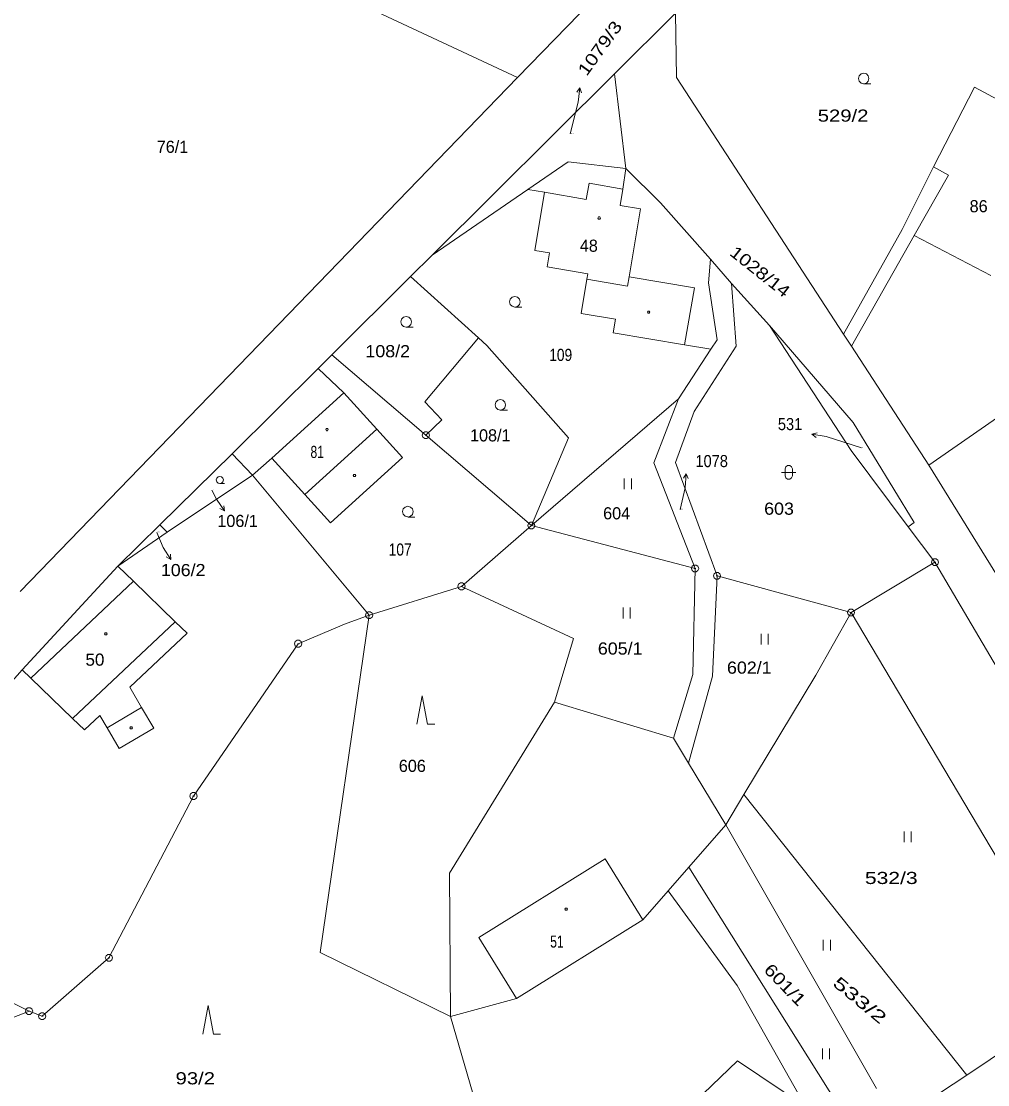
# Model space of a CAD drawing. Extents: x -687390 to -684106, y -954833 to -951648.
# Drawn here: x -687069.7 to -686934.3, y -952895.8 to -952746.6 of the extents above; entities that cross this region are included whole.
import ezdxf
from ezdxf.enums import TextEntityAlignment as Align

# ---------------------------------------------------------------- set-up
doc = ezdxf.new("R2010")
doc.units = 0
doc.header["$LTSCALE"] = 0.68
for name, color, linetype, lineweight in [('1', 7, 'Continuous', 13), ('3', 7, 'Continuous', 13), ('4', 7, 'Continuous', 13), ('5', 7, 'Continuous', 13), ('7', 7, 'Continuous', 13), ('8', 7, 'Continuous', 13)]:
    doc.layers.add(name, color=color, linetype=linetype, lineweight=lineweight)
doc.layers.add('2', color=7, linetype='Continuous')

msp = doc.modelspace()

# ---------------------------------------------------------------- linework, layer by layer
at = {"layer": '1'}
for p, q in [((-687044.3, -952733.87), (-687000.19, -952754.54)), ((-686978.03, -952745.51), (-686986.58, -952754.02)), ((-686984.99, -952767.3), (-686986.58, -952754.02)), ((-686921.94, -952763.55), (-686936.14, -952755.87)), ((-686984.99, -952767.3), (-686993.1, -952766.34)), ((-686984.99, -952767.3), (-686980.16, -952772.08)), ((-686996.42, -952770.6), (-686998.74, -952770.21)), ((-686980.16, -952772.08), (-686973.12, -952780)), ((-686954.5, -952790.5), (-686946.27, -952775.82)), ((-686944.59, -952776.68), (-686953.39, -952792.2)), ((-686933.85, -952782.3), (-686944.59, -952776.68)), ((-687015.17, -952782.45), (-687026.22, -952793.42)), ((-687015.17, -952782.45), (-687005.65, -952791.03)), ((-686964.87, -952789.29), (-686953.14, -952802.92)), ((-687005.65, -952791.03), (-687004.48, -952792.09)), ((-686986.77, -952790.31), (-686976.76, -952792)), ((-686973.08, -952792.63), (-686976.76, -952792)), ((-687026.22, -952793.42), (-687013.03, -952804.69)), ((-687024.54, -952798.73), (-687028.14, -952795.33)), ((-687024.54, -952798.73), (-687019.92, -952803.82)), ((-686998.24, -952817.35), (-686977.64, -952799.56)), ((-686977.64, -952799.56), (-686981.08, -952808.54)), ((-686944.6, -952816.91), (-686953.14, -952802.92)), ((-687019.92, -952803.82), (-687016.32, -952807.8)), ((-687013.03, -952804.69), (-686998.24, -952817.35)), ((-687040.16, -952807.28), (-687037.34, -952810.27)), ((-687037.34, -952810.27), (-687034.64, -952807.89)), ((-687030.01, -952812.99), (-687034.64, -952807.89)), ((-687026.41, -952816.95), (-687016.32, -952807.8)), ((-686975.29, -952823.36), (-686981.08, -952808.54)), ((-687037.34, -952810.27), (-687020.98, -952829.91)), ((-687030.01, -952812.99), (-687026.41, -952816.95)), ((-687050.32, -952817.26), (-687049.31, -952818.29)), ((-686944.6, -952816.91), (-686945.41, -952817.51)), ((-686972.22, -952824.4), (-686972.87, -952838.46)), ((-687020.98, -952829.91), (-687024.42, -952831.17)), ((-686958.39, -952838.32), (-686953.43, -952829.54)), ((-686953.43, -952829.54), (-686920.81, -952884.49)), ((-687048.15, -952830.85), (-687046.5, -952832.45)), ((-687030.92, -952833.92), (-687024.42, -952831.17)), ((-687046.5, -952832.45), (-687054.54, -952840.02)), ((-687068.42, -952838.73), (-687069.6, -952837.58)), ((-686972.87, -952838.46), (-686976.2, -952850.66)), ((-687052.87, -952842.84), (-687054.54, -952840.02)), ((-687051.15, -952845.76), (-687052.87, -952842.84)), ((-687058.74, -952843.97), (-687060.9, -952846.01)), ((-687058.74, -952843.97), (-687057.72, -952845.7)), ((-687057.72, -952845.7), (-687056, -952848.63)), ((-687056, -952848.63), (-687051.15, -952845.76)), ((-686968.45, -952855.08), (-686937.22, -952894.39)), ((-686970.99, -952859.32), (-686949.85, -952896.26)), ((-686955.03, -952899), (-686976.16, -952865.23)), ((-686979.07, -952868.55), (-686969.38, -952881.84)), ((-687068.64, -952885.43), (-687097.68, -952871.23))]:
    msp.add_line(p, q, dxfattribs=at)
for points in [[(-686977.91, -952754.52), (-686978.03, -952745.51), (-686968.52, -952733.75)], [(-686986.33, -952740.23), (-687000.19, -952754.54), (-687069.88, -952826.59)], [(-686986.58, -952754.02), (-687012.16, -952779.46), (-687015.17, -952782.45)], [(-686977.91, -952754.52), (-686954.5, -952790.5), (-686953.39, -952792.2), (-686942.54, -952808.88)], [(-686936.14, -952755.87), (-686941.89, -952767.04), (-686946.27, -952775.82)], [(-686993.1, -952766.34), (-686998.74, -952770.21), (-687012.16, -952779.46)], [(-686996.42, -952770.6), (-686997.76, -952778.78), (-686995.69, -952779.12), (-686996.02, -952781.09), (-686990.33, -952782.04)], [(-686942.54, -952808.88), (-686900.19, -952779.49), (-686902.11, -952775.53)], [(-686973.12, -952780), (-686970.18, -952783.41), (-686969.53, -952792.18), (-686975.41, -952801.38), (-686978.06, -952808.49), (-686972.22, -952824.4)], [(-686972.21, -952791.3), (-686973.43, -952783.33), (-686973.12, -952780)], [(-686990.33, -952782.04), (-686990.46, -952782.82), (-686991.26, -952787.62)], [(-686970.18, -952783.41), (-686964.87, -952789.29), (-686953.42, -952806.81)], [(-686991.26, -952787.62), (-686986.45, -952788.42), (-686986.77, -952790.31)], [(-687013.03, -952804.69), (-687010.77, -952802.53), (-687013.19, -952800.02), (-687005.65, -952791.03)], [(-686998.24, -952817.35), (-686993.04, -952805.03), (-687004.48, -952792.09)], [(-686977.64, -952799.56), (-686973.08, -952792.63), (-686972.21, -952791.3)], [(-687026.22, -952793.42), (-687028.14, -952795.33), (-687040.16, -952807.28)], [(-687056.2, -952823.03), (-687050.32, -952817.26), (-687040.16, -952807.28)], [(-686941.67, -952822.48), (-686945.41, -952817.51), (-686953.42, -952806.81)], [(-686942.54, -952808.88), (-686931.71, -952826.41), (-686920.73, -952825.17)], [(-687056.2, -952823.03), (-687049.31, -952818.29), (-687037.34, -952810.27)], [(-687020.98, -952829.91), (-687008.03, -952825.88), (-686998.24, -952817.35), (-686975.29, -952823.36)], [(-686972.22, -952824.4), (-686953.43, -952829.54), (-686941.67, -952822.48)], [(-686901.42, -952870.78), (-686906.16, -952871.49), (-686915.95, -952866.19), (-686941.67, -952822.48)], [(-687076.25, -952845.06), (-687069.6, -952837.58), (-687056.2, -952823.03)], [(-687056.2, -952823.03), (-687054.02, -952825.15), (-687048.15, -952830.85)], [(-687008.03, -952825.88), (-686992.32, -952833.2), (-686995.02, -952842.1), (-686978.32, -952847.16), (-686975.61, -952838.21), (-686975.29, -952823.36)], [(-687009.56, -952886.19), (-687027.83, -952877.22), (-687020.98, -952829.91)], [(-687069.27, -952916.95), (-687084.32, -952891.61), (-687068.64, -952885.43), (-687066.8, -952886.15), (-687057.45, -952877.97), (-687045.6, -952855.28), (-687030.92, -952833.92)], [(-687060.9, -952846.01), (-687062.55, -952844.41), (-687068.42, -952838.73)], [(-686970.99, -952859.32), (-686968.45, -952855.08), (-686958.39, -952838.32)], [(-686995.02, -952842.1), (-687009.71, -952866.08), (-687009.56, -952886.19)], [(-686978.32, -952847.16), (-686976.2, -952850.66), (-686970.99, -952859.32)], [(-686970.99, -952859.32), (-686976.16, -952865.23), (-686979.07, -952868.55)], [(-686969.38, -952881.84), (-686959.84, -952898.79), (-686969.35, -952892.4), (-687003.06, -952924.79), (-687017.89, -952911.13), (-687004.48, -952903.7), (-687009.56, -952886.19)], [(-686930.65, -952890.02), (-686937.22, -952894.39), (-686947.05, -952900.93)]]:
    msp.add_lwpolyline(points, dxfattribs=at)
at = {"layer": '3'}
for p, q in [((-686985.22, -952810.76), (-686985.22, -952812.26)), ((-686984.22, -952812.26), (-686984.22, -952810.76)), ((-686985.39, -952828.86), (-686985.39, -952830.36)), ((-686984.39, -952830.36), (-686984.39, -952828.86)), ((-686966.04, -952832.53), (-686966.04, -952834.03)), ((-686965.04, -952834.03), (-686965.04, -952832.53)), ((-686946.01, -952860.26), (-686946.01, -952861.76)), ((-686945.01, -952861.76), (-686945.01, -952860.26)), ((-686957.32, -952875.42), (-686957.32, -952876.92)), ((-686956.32, -952876.92), (-686956.32, -952875.42)), ((-686957.45, -952890.67), (-686957.45, -952892.17)), ((-686956.45, -952892.17), (-686956.45, -952890.67))]:
    msp.add_line(p, q, dxfattribs=at)
for points in [[(-686951.65, -952755.4), (-686952.03, -952755.3), (-686952.3, -952755.03), (-686952.4, -952754.66), (-686952.3, -952754.29), (-686952.03, -952754.02), (-686951.66, -952753.92), (-686951.29, -952754.02), (-686951.02, -952754.29), (-686950.92, -952754.67), (-686951.02, -952755.05), (-686951.29, -952755.32), (-686951.67, -952755.42), (-686950.67, -952755.42)], [(-687000.55, -952786.71), (-687000.93, -952786.61), (-687001.2, -952786.34), (-687001.3, -952785.97), (-687001.2, -952785.6), (-687000.93, -952785.33), (-687000.56, -952785.23), (-687000.19, -952785.33), (-686999.92, -952785.6), (-686999.82, -952785.98), (-686999.92, -952786.36), (-687000.19, -952786.63), (-687000.57, -952786.73), (-686999.57, -952786.73)], [(-687015.79, -952789.52), (-687016.17, -952789.42), (-687016.44, -952789.15), (-687016.54, -952788.78), (-687016.44, -952788.41), (-687016.17, -952788.14), (-687015.8, -952788.04), (-687015.43, -952788.14), (-687015.16, -952788.41), (-687015.06, -952788.79), (-687015.16, -952789.17), (-687015.43, -952789.44), (-687015.81, -952789.54), (-687014.81, -952789.54)], [(-687002.58, -952801.17), (-687002.96, -952801.07), (-687003.23, -952800.8), (-687003.33, -952800.43), (-687003.23, -952800.06), (-687002.96, -952799.79), (-687002.59, -952799.69), (-687002.22, -952799.79), (-687001.95, -952800.06), (-687001.85, -952800.44), (-687001.95, -952800.82), (-687002.22, -952801.09), (-687002.6, -952801.19), (-687001.6, -952801.19)], [(-687041.9, -952811.45), (-687042.155, -952811.383), (-687042.336, -952811.202), (-687042.402, -952810.954), (-687042.336, -952810.706), (-687042.155, -952810.525), (-687041.907, -952810.458), (-687041.659, -952810.525), (-687041.478, -952810.706), (-687041.411, -952810.961), (-687041.478, -952811.215), (-687041.659, -952811.396), (-687041.913, -952811.463), (-687041.243, -952811.463)], [(-686963.17, -952809.89), (-686961.9, -952809.89), (-686961.17, -952809.89)], [(-687015.55, -952816.13), (-687015.93, -952816.03), (-687016.2, -952815.76), (-687016.3, -952815.39), (-687016.2, -952815.02), (-687015.93, -952814.75), (-687015.56, -952814.65), (-687015.19, -952814.75), (-687014.92, -952815.02), (-687014.82, -952815.4), (-687014.92, -952815.78), (-687015.19, -952816.05), (-687015.57, -952816.15), (-687014.57, -952816.15)], [(-687014.28, -952845.22), (-687013.53, -952841.22), (-687012.78, -952845.22), (-687011.78, -952845.22)], [(-687044.3, -952888.66), (-687043.55, -952884.66), (-687042.8, -952888.66), (-687041.8, -952888.66)]]:
    msp.add_lwpolyline(points, dxfattribs=at)
msp.add_lwpolyline([(-686962.67, -952809.39), (-686962.57, -952809.1), (-686962.32, -952808.92), (-686962.01, -952808.92), (-686961.76, -952809.1), (-686961.66, -952809.39), (-686961.66, -952810.39), (-686961.76, -952810.68), (-686962.01, -952810.86), (-686962.32, -952810.86), (-686962.57, -952810.68), (-686962.67, -952810.39)], close=True, dxfattribs=at)
at = {"layer": '4'}
for p, q in [((-686985.41, -952770.18), (-686985.79, -952772.47)), ((-686982.93, -952772.95), (-686985.79, -952772.47)), ((-686982.93, -952772.95), (-686984.54, -952782.46)), ((-686990.46, -952782.82), (-686984.76, -952783.77)), ((-686984.54, -952782.46), (-686984.76, -952783.77)), ((-687024.54, -952798.73), (-687034.64, -952807.89)), ((-687030.01, -952812.99), (-687019.92, -952803.82)), ((-687054.02, -952825.15), (-687068.42, -952838.73)), ((-687048.15, -952830.85), (-687062.55, -952844.41)), ((-687057.72, -952845.7), (-687052.87, -952842.84)), ((-686987.89, -952864.07), (-686982.62, -952872.62)), ((-686979.07, -952868.55), (-686982.62, -952872.62)), ((-686982.62, -952872.62), (-687000.34, -952883.65)), ((-687009.56, -952886.19), (-687000.34, -952883.65))]:
    msp.add_line(p, q, dxfattribs=at)
for points in [[(-686996.42, -952770.6), (-686990.54, -952771.62), (-686990.14, -952769.33), (-686985.41, -952770.18), (-686984.99, -952767.3)], [(-686944.59, -952776.68), (-686939.79, -952768.23), (-686941.89, -952767.04)], [(-686976.76, -952792), (-686975.4, -952784.01), (-686984.54, -952782.46)], [(-686987.89, -952864.07), (-687005.61, -952875.1), (-687000.34, -952883.65)]]:
    msp.add_lwpolyline(points, dxfattribs=at)
at = {"layer": '5'}
for points in [[(-686988.66, -952774.08), (-686988.57, -952774.23), (-686988.66, -952774.38), (-686988.84, -952774.38), (-686988.93, -952774.23), (-686988.84, -952774.08)], [(-686981.71, -952787.28), (-686981.62, -952787.43), (-686981.71, -952787.58), (-686981.89, -952787.58), (-686981.98, -952787.43), (-686981.89, -952787.28)], [(-687026.8, -952803.75), (-687026.71, -952803.9), (-687026.8, -952804.05), (-687026.98, -952804.05), (-687027.07, -952803.9), (-687026.98, -952803.75)], [(-687022.96, -952810.17), (-687022.87, -952810.32), (-687022.96, -952810.47), (-687023.14, -952810.47), (-687023.23, -952810.32), (-687023.14, -952810.17)], [(-687057.81, -952832.38), (-687057.72, -952832.53), (-687057.81, -952832.68), (-687057.99, -952832.68), (-687058.08, -952832.53), (-687057.99, -952832.38)], [(-687054.25, -952845.56), (-687054.16, -952845.71), (-687054.25, -952845.86), (-687054.43, -952845.86), (-687054.52, -952845.71), (-687054.43, -952845.56)], [(-686993.29, -952870.98), (-686993.2, -952871.13), (-686993.29, -952871.28), (-686993.47, -952871.28), (-686993.56, -952871.13), (-686993.47, -952870.98)]]:
    msp.add_lwpolyline(points, close=True, dxfattribs=at)
at = {"layer": '7'}
for p, q in [((-686991.465, -952755.972), (-686991.68, -952757.97)), ((-686992.81, -952762.42), (-686991.68, -952757.97)), ((-686958.922, -952804.546), (-686956.94, -952804.88)), ((-686951.95, -952806.47), (-686956.94, -952804.88)), ((-686976.535, -952810.077), (-686976.7, -952812.08)), ((-686977.38, -952815.1), (-686976.7, -952812.08)), ((-687043.04, -952812.37), (-687042.39, -952813.66)), ((-687041.235, -952815.305), (-687042.39, -952813.66)), ((-687050.73, -952818.31), (-687049.83, -952820.41)), ((-687048.786, -952822.127), (-687049.83, -952820.41))]:
    msp.add_line(p, q, dxfattribs=at)
for points in [[(-686991.87, -952756.602), (-686991.465, -952755.972), (-686991.204, -952756.674)], [(-686958.317, -952804.988), (-686958.922, -952804.546), (-686958.206, -952804.327)], [(-686976.924, -952810.717), (-686976.535, -952810.077), (-686976.256, -952810.772)], [(-687041.346, -952814.564), (-687041.235, -952815.305), (-687041.894, -952814.949)], [(-687048.847, -952821.381), (-687048.786, -952822.127), (-687049.42, -952821.729)]]:
    msp.add_lwpolyline(points, dxfattribs=at)
at = {"layer": '8'}
for p, q in [((-687013.15, -952804.69), (-687012.91, -952804.69)), ((-686998.36, -952817.35), (-686998.12, -952817.35)), ((-686941.79, -952822.48), (-686941.55, -952822.48)), ((-686975.41, -952823.36), (-686975.17, -952823.36)), ((-686972.34, -952824.4), (-686972.1, -952824.4)), ((-687008.15, -952825.88), (-687007.91, -952825.88)), ((-687021.1, -952829.91), (-687020.86, -952829.91)), ((-686953.55, -952829.54), (-686953.31, -952829.54)), ((-687031.04, -952833.92), (-687030.8, -952833.92)), ((-687045.72, -952855.28), (-687045.48, -952855.28)), ((-687057.57, -952877.97), (-687057.33, -952877.97)), ((-687068.76, -952885.43), (-687068.52, -952885.43)), ((-687066.92, -952886.15), (-687066.68, -952886.15))]:
    msp.add_line(p, q, dxfattribs=at)
for points in [[(-687012.88, -952804.21), (-687012.63, -952804.39), (-687012.53, -952804.68), (-687012.63, -952804.97), (-687012.88, -952805.15), (-687013.19, -952805.15), (-687013.44, -952804.97), (-687013.54, -952804.68), (-687013.44, -952804.39), (-687013.19, -952804.21)], [(-686998.09, -952816.87), (-686997.84, -952817.05), (-686997.74, -952817.34), (-686997.84, -952817.63), (-686998.09, -952817.81), (-686998.4, -952817.81), (-686998.65, -952817.63), (-686998.75, -952817.34), (-686998.65, -952817.05), (-686998.4, -952816.87)], [(-686941.52, -952822), (-686941.27, -952822.18), (-686941.17, -952822.47), (-686941.27, -952822.76), (-686941.52, -952822.94), (-686941.83, -952822.94), (-686942.08, -952822.76), (-686942.18, -952822.47), (-686942.08, -952822.18), (-686941.83, -952822)], [(-686975.14, -952822.88), (-686974.89, -952823.06), (-686974.79, -952823.35), (-686974.89, -952823.64), (-686975.14, -952823.82), (-686975.45, -952823.82), (-686975.7, -952823.64), (-686975.8, -952823.35), (-686975.7, -952823.06), (-686975.45, -952822.88)], [(-686972.07, -952823.92), (-686971.82, -952824.1), (-686971.72, -952824.39), (-686971.82, -952824.68), (-686972.07, -952824.86), (-686972.38, -952824.86), (-686972.63, -952824.68), (-686972.73, -952824.39), (-686972.63, -952824.1), (-686972.38, -952823.92)], [(-687007.88, -952825.4), (-687007.63, -952825.58), (-687007.53, -952825.87), (-687007.63, -952826.16), (-687007.88, -952826.34), (-687008.19, -952826.34), (-687008.44, -952826.16), (-687008.54, -952825.87), (-687008.44, -952825.58), (-687008.19, -952825.4)], [(-687020.83, -952829.43), (-687020.58, -952829.61), (-687020.48, -952829.9), (-687020.58, -952830.19), (-687020.83, -952830.37), (-687021.14, -952830.37), (-687021.39, -952830.19), (-687021.49, -952829.9), (-687021.39, -952829.61), (-687021.14, -952829.43)], [(-686953.28, -952829.06), (-686953.03, -952829.24), (-686952.93, -952829.53), (-686953.03, -952829.82), (-686953.28, -952830), (-686953.59, -952830), (-686953.84, -952829.82), (-686953.94, -952829.53), (-686953.84, -952829.24), (-686953.59, -952829.06)], [(-687030.77, -952833.44), (-687030.52, -952833.62), (-687030.42, -952833.91), (-687030.52, -952834.2), (-687030.77, -952834.38), (-687031.08, -952834.38), (-687031.33, -952834.2), (-687031.43, -952833.91), (-687031.33, -952833.62), (-687031.08, -952833.44)], [(-687045.45, -952854.8), (-687045.2, -952854.98), (-687045.1, -952855.27), (-687045.2, -952855.56), (-687045.45, -952855.74), (-687045.76, -952855.74), (-687046.01, -952855.56), (-687046.11, -952855.27), (-687046.01, -952854.98), (-687045.76, -952854.8)], [(-687057.3, -952877.49), (-687057.05, -952877.67), (-687056.95, -952877.96), (-687057.05, -952878.25), (-687057.3, -952878.43), (-687057.61, -952878.43), (-687057.86, -952878.25), (-687057.96, -952877.96), (-687057.86, -952877.67), (-687057.61, -952877.49)], [(-687068.49, -952884.95), (-687068.24, -952885.13), (-687068.14, -952885.42), (-687068.24, -952885.71), (-687068.49, -952885.89), (-687068.8, -952885.89), (-687069.05, -952885.71), (-687069.15, -952885.42), (-687069.05, -952885.13), (-687068.8, -952884.95)], [(-687066.65, -952885.67), (-687066.4, -952885.85), (-687066.3, -952886.14), (-687066.4, -952886.43), (-687066.65, -952886.61), (-687066.96, -952886.61), (-687067.21, -952886.43), (-687067.31, -952886.14), (-687067.21, -952885.85), (-687066.96, -952885.67)]]:
    msp.add_lwpolyline(points, close=True, dxfattribs=at)

# ---------------------------------------------------------------- texts
at = {"layer": '2'}
for s, height, width, p in [('529/2', 1.7, 1.25, (-686958.105, -952760.72)), ('1079/3', 0.1, 1.1, (-686992.764, -952762.42)), ('108/2', 1.7, 1.1, (-687021.505, -952793.75)), ('109', 1.7, 0.85, (-686995.745, -952794.27)), ('81', 1.7, 0.75, (-687029.205, -952807.87)), ('531', 0.1, 0.9, (-686951.922, -952806.47)), ('1078', 0.1, 0.9, (-686977.334, -952815.1)), ('603', 1.7, 1.1, (-686965.616, -952815.83)), ('106/2', 0.1, 1.1, (-687050.684, -952818.31)), ('107', 1.7, 0.85, (-687018.245, -952821.56)), ('605/1', 1.7, 1.1, (-686988.926, -952835.44)), ('50', 1.7, 1.05, (-687060.745, -952837)), ('602/1', 1.7, 1.1, (-686970.826, -952838.12)), ('532/3', 1.7, 1.3, (-686951.495, -952867.61)), ('51', 1.7, 0.75, (-686995.605, -952876.53)), ('93/2', 1.7, 1.25, (-687048.115, -952895.7))]:
    msp.add_text(s, height=height, dxfattribs=dict(at, width=width)).set_placement(p)
for s, height, p in [('76/1', 1.7, (-687050.755, -952765.09)), ('86', 1.7, (-686936.815, -952773.42)), ('48', 1.7, (-686991.455, -952778.96)), ('108/1', 1.7, (-687006.845, -952805.55)), ('106/1', 0.1, (-687042.994, -952812.37)), ('604', 1.7, (-686988.186, -952816.48)), ('606', 1.7, (-687016.826, -952851.89))]:
    msp.add_text(s, height=height, dxfattribs=at).set_placement(p)
for s, rotation, width, p in [('1028/14', 321.601, 1.2, (-686970.574, -952779.348)), ('601/1', 314.038, 1.25, (-686965.774, -952879.763)), ('533/2', 320.513, 1.55, (-686956.144, -952881.752))]:
    msp.add_text(s, height=1.7, rotation=rotation, dxfattribs=dict(at, width=width)).set_placement(p)
at = {"layer": '7', "width": 1.25}
msp.add_text('1079/3', height=1.7, rotation=54.259, dxfattribs=at).set_placement((-686990.491, -952754.433))
at = {"layer": '7', "width": 0.9}
msp.add_text('531', height=1.7, dxfattribs=at).set_placement((-686960.276, -952803.97), align=Align.RIGHT)
at = {"layer": '7'}
for s, width, p in [('1078', 0.9, (-686975.245, -952809.16)), ('106/2', 1.1, (-687050.175, -952824.44))]:
    msp.add_text(s, height=1.7, dxfattribs=dict(at, width=width)).set_placement(p)
msp.add_text('106/1', height=1.7, dxfattribs=at).set_placement((-687042.265, -952817.55))

doc.saveas('drawing.dxf')
